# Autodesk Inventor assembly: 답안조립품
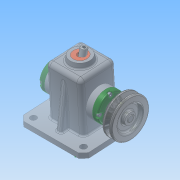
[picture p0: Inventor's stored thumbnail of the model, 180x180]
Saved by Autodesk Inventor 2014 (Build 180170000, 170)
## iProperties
Created: 2016-02
Part Number: 답안조립품
Document SubType Name: Assembly
Designer: net
Author: net
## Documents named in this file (15)
- C:\Users\net\Desktop\460211V1021\460211V1021\답안조립품.iam
- C:\Users\net\Desktop\460211V1021\460211V1021\본체.ipt
- C:\Users\net\Desktop\460211V1021\460211V1021\편심축.ipt
- C:\Users\net\Desktop\460211V1021\460211V1021\뒤커버.ipt
- C:\Users\net\Desktop\460211V1021\460211V1021\앞커버.ipt
- C:\Users\net\Desktop\460211V1021\460211V1021\볼트 M4 x 12.ipt
- C:\Users\net\Desktop\460211V1021\460211V1021\슬라이드.ipt
- C:\Users\net\Desktop\460211V1021\460211V1021\베어링 12 x 32 x 10.ipt
- C:\Users\net\Desktop\460211V1021\460211V1021\고정핀 1.2 x 10.ipt
- C:\Users\net\Desktop\460211V1021\460211V1021\핀 5 x 18.ipt
- C:\Users\net\Desktop\460211V1021\460211V1021\링크.ipt
- C:\Users\net\Desktop\460211V1021\460211V1021\오일실 12 25 7.ipt
- C:\Users\net\Desktop\460211V1021\460211V1021\키 4 x 4 x 10.ipt
- C:\Users\net\Desktop\460211V1021\460211V1021\V벨트풀리.ipt
- C:\Users\net\Desktop\460211V1021\460211V1021\부시.ipt
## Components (11 placed, 4 different names)
1. 고정핀 1.2 x 10:1
2. 핀 5 x 18:1
3. V벨트풀리:1 — 각도:1
4. ISO 4762 M4 x 12:1
5. ISO 4762 M4 x 12:2
6. ISO 4762 M4 x 12:3
7. ISO 4762 M4 x 12:4
8. ISO 4762 M4 x 12:5
9. ISO 4762 M4 x 12:6
10. ISO 4762 M4 x 12:7
11. ISO 4762 M4 x 12:8
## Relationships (1: Angle 1)
- 각도:1 [Angle]: V벨트풀리:1
